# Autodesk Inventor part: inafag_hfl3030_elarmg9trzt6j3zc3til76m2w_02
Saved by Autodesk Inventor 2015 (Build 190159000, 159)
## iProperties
Company: TraceParts S.A.
Created: 2012-12
Part Number: inafag_hfl3030_elarmg9trzt6j3zc3til76m2w_02
Checked By: TraceParts S.A.
Catalog Web Link: www.traceparts.com
Document SubType Name: Modeling
Designer: TraceParts
Material: Generic
Density: 1 g/cm^3
Appearance: Default
Author: TraceParts
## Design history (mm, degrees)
feature "inafag_hfl3030_elarmg9trzt6j3zc3til76m2w"
body "Solid1"
